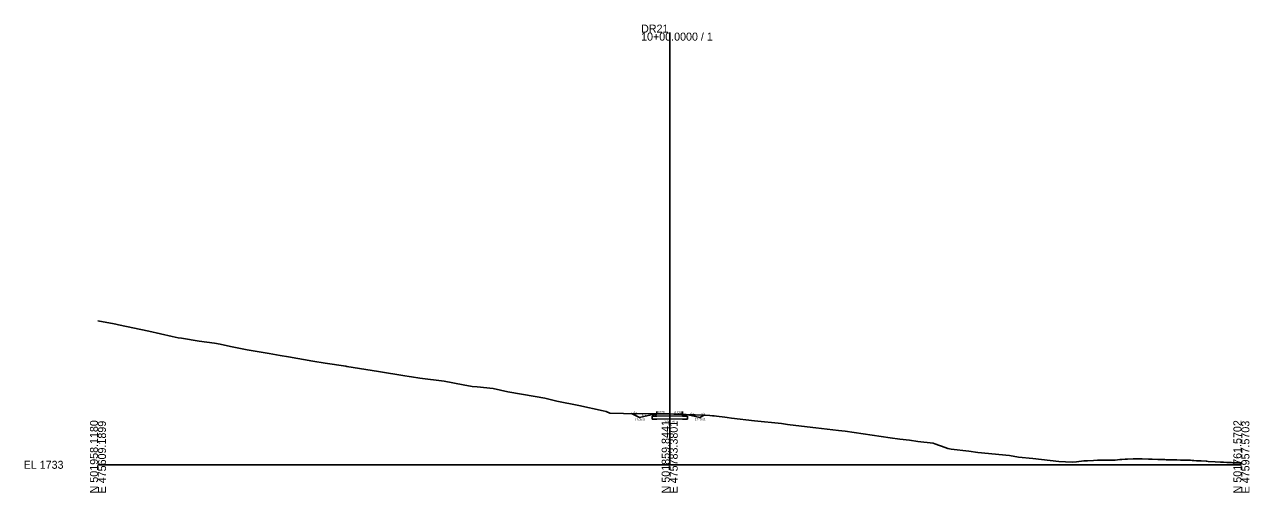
# Model space of a CAD drawing. Extents: x 78347 to 78775, y -92484 to -91314.
# Drawn here: x 78346.7 to 78775.2, y -92483.8 to -92320.1 of the extents above; entities that cross this region are included whole.
import ezdxf

# ---------------------------------------------------------------- set-up
doc = ezdxf.new("R2010")
doc.units = 0
for name, color, linetype in [('Exist Cross Section Cell', 7, 'Continuous'), ('Exist XS Center Line Elevation Label', 7, 'Continuous'), ('Exist XS Ground Line', 7, 'Continuous'), ('Prop CMT Shallow Undercut Boundary', 7, 'Continuous'), ('Prop XS Ditch Slope Text', 7, 'Continuous'), ('Prop XS Ditch Standard Text', 7, 'Continuous'), ('Prop XS Earthwork Shape', 7, 'Continuous'), ('Prop XS EOT Tick Mark', 7, 'Continuous'), ('Prop XS Finish Grade', 7, 'Continuous'), ('Prop XS Finish Grade Earthwork', 7, 'Continuous'), ('Prop XS Finish Grade Pavement', 7, 'Continuous'), ('Prop XS Pvmt Edge Slope', 7, 'Continuous'), ('Prop XS SE Text', 7, 'Continuous'), ('Prop XS Shoulder Borrow Shape', 7, 'Continuous'), ('Prop XS Side Slope Text', 7, 'Continuous'), ('Prop XS Subgrade Earthwork', 7, 'Continuous')]:
    doc.layers.add(name, color=color, linetype=linetype)

msp = doc.modelspace()

# ---------------------------------------------------------------- linework, layer by layer
at = {"layer": 'Exist Cross Section Cell'}
for p, q in [((78572.41, -92474.1), (78572.41, -92322.94)), ((78372.41, -92474.1), (78572.41, -92474.1)), ((78572.41, -92474.1), (78772.41, -92474.1))]:
    msp.add_line(p, q, dxfattribs=at)
at = {"layer": 'Exist XS Ground Line'}
for p, q in [((78372.41, -92423.71), (78378.03, -92424.8)), ((78378.03, -92424.8), (78378.7, -92424.94)), ((78378.7, -92424.94), (78379.56, -92425.12)), ((78379.56, -92425.12), (78390.18, -92427.4)), ((78390.18, -92427.4), (78398.39, -92429.19)), ((78398.39, -92429.19), (78400.48, -92429.64)), ((78400.48, -92429.64), (78401.67, -92429.86)), ((78401.67, -92429.86), (78407.83, -92430.9)), ((78407.83, -92430.9), (78413.15, -92431.57)), ((78413.15, -92431.57), (78415.17, -92431.96)), ((78415.17, -92431.96), (78418.74, -92432.72)), ((78418.74, -92432.72), (78424.64, -92433.87)), ((78424.64, -92433.87), (78432.26, -92435.18)), ((78432.26, -92435.18), (78436.12, -92435.82)), ((78436.12, -92435.82), (78439.1, -92436.34)), ((78439.1, -92436.34), (78447.6, -92437.81)), ((78447.6, -92437.81), (78451.88, -92438.57)), ((78451.88, -92438.57), (78459.09, -92439.66)), ((78459.09, -92439.66), (78459.45, -92439.73)), ((78459.45, -92439.73), (78470.57, -92441.52)), ((78470.57, -92441.52), (78479.81, -92443.02)), ((78479.81, -92443.02), (78481.24, -92443.27)), ((78481.24, -92443.27), (78482.05, -92443.38)), ((78482.05, -92443.38), (78484.96, -92443.81)), ((78484.96, -92443.81), (78493.54, -92444.9)), ((78493.54, -92444.9), (78500.16, -92446.13)), ((78500.16, -92446.13), (78503.27, -92446.66)), ((78503.27, -92446.66), (78505.02, -92446.89)), ((78505.02, -92446.89), (78510.61, -92447.45)), ((78510.61, -92447.45), (78515.82, -92448.56)), ((78515.82, -92448.56), (78525.35, -92450.21)), ((78525.35, -92450.21), (78528.68, -92450.85)), ((78528.68, -92450.85), (78532.92, -92451.9)), ((78532.92, -92451.9), (78540.6, -92453.31)), ((78540.6, -92453.31), (78549.2, -92455.23)), ((78549.2, -92455.23), (78550.15, -92455.49)), ((78550.15, -92455.49), (78551.49, -92456.07)), ((78551.49, -92456.07), (78556.26, -92456.15)), ((78556.26, -92456.15), (78568.78, -92456.27)), ((78568.78, -92456.27), (78572.41, -92456.33)), ((78572.41, -92456.33), (78573.92, -92456.36)), ((78573.92, -92456.36), (78576.67, -92456.46)), ((78576.67, -92456.46), (78577.52, -92456.47)), ((78577.52, -92456.47), (78578.21, -92456.5)), ((78578.21, -92456.5), (78586.45, -92456.89)), ((78586.45, -92456.89), (78587.35, -92456.92)), ((78587.35, -92456.92), (78587.96, -92456.98)), ((78587.96, -92456.98), (78588.78, -92457.09)), ((78588.78, -92457.09), (78591.73, -92457.41)), ((78591.73, -92457.41), (78592.56, -92457.54)), ((78592.56, -92457.54), (78593.98, -92457.83)), ((78593.98, -92457.83), (78602.04, -92458.67)), ((78602.04, -92458.67), (78611.55, -92459.66)), ((78611.55, -92459.66), (78613.64, -92459.96)), ((78613.64, -92459.96), (78614.6, -92460.07)), ((78614.6, -92460.07), (78623.5, -92461.14)), ((78623.5, -92461.14), (78631.48, -92462.07)), ((78631.48, -92462.07), (78633.82, -92462.33)), ((78633.82, -92462.33), (78649.56, -92464.7)), ((78649.56, -92464.7), (78652.98, -92465.18)), ((78652.98, -92465.18), (78656.34, -92465.54)), ((78656.34, -92465.54), (78659.17, -92466.01)), ((78659.17, -92466.01), (78664.61, -92466.59)), ((78664.61, -92466.59), (78665.22, -92466.76)), ((78665.22, -92466.76), (78668.8, -92468)), ((78668.8, -92468), (78669.66, -92468.36)), ((78669.66, -92468.36), (78670.86, -92468.58)), ((78670.86, -92468.58), (78677.08, -92469.39)), ((78677.08, -92469.39), (78680.26, -92469.79)), ((78680.26, -92469.79), (78691.31, -92470.88)), ((78691.31, -92470.88), (78694.42, -92471.38)), ((78694.42, -92471.38), (78699.45, -92471.91)), ((78699.45, -92471.91), (78708.49, -92472.9)), ((78708.49, -92472.9), (78710.84, -92473.12)), ((78714.72, -92473.1), (78717.26, -92472.73)), ((78717.26, -92472.73), (78718.11, -92472.68)), ((78718.11, -92472.68), (78718.61, -92472.67)), ((78718.61, -92472.67), (78720.71, -92472.58)), ((78720.71, -92472.58), (78722.08, -92472.49)), ((78722.08, -92472.49), (78722.86, -92472.5)), ((78722.86, -92472.5), (78728.06, -92472.5)), ((78728.06, -92472.5), (78728.21, -92472.49)), ((78728.21, -92472.49), (78729.85, -92472.27)), ((78729.85, -92472.27), (78729.95, -92472.27)), ((78729.95, -92472.27), (78730.56, -92472.22)), ((78730.56, -92472.22), (78731.71, -92472.12)), ((78731.71, -92472.12), (78732.62, -92472.08)), ((78732.62, -92472.08), (78734.59, -92472)), ((78734.59, -92472), (78734.62, -92472)), ((78734.62, -92472), (78734.78, -92472)), ((78734.78, -92472), (78734.91, -92472.01)), ((78734.91, -92472.01), (78735.63, -92472.02)), ((78735.63, -92472.02), (78737.05, -92472.05)), ((78737.05, -92472.05), (78737.36, -92472.06)), ((78737.36, -92472.06), (78737.65, -92472.07)), ((78737.65, -92472.07), (78739.94, -92472.14)), ((78739.94, -92472.14), (78740.31, -92472.16)), ((78740.31, -92472.16), (78741.15, -92472.18)), ((78741.15, -92472.18), (78743.17, -92472.23)), ((78743.17, -92472.23), (78744.72, -92472.27)), ((78744.72, -92472.27), (78745.57, -92472.3)), ((78745.57, -92472.3), (78746.05, -92472.31)), ((78746.05, -92472.31), (78747.42, -92472.35)), ((78747.42, -92472.35), (78748.92, -92472.39)), ((78748.92, -92472.39), (78749.82, -92472.41)), ((78749.82, -92472.41), (78751.05, -92472.44)), ((78751.05, -92472.44), (78751.76, -92472.46)), ((78751.76, -92472.46), (78753.04, -92472.51)), ((78753.04, -92472.51), (78754.66, -92472.54)), ((78754.66, -92472.54), (78755.15, -92472.57)), ((78755.15, -92472.57), (78755.82, -92472.6)), ((78755.82, -92472.6), (78756.68, -92472.66)), ((78756.68, -92472.66), (78757.5, -92472.71)), ((78757.5, -92472.71), (78758.38, -92472.76)), ((78758.38, -92472.76), (78760.03, -92472.85)), ((78760.03, -92472.85), (78760.17, -92472.86)), ((78760.17, -92472.86), (78760.36, -92472.87)), ((78760.36, -92472.87), (78760.79, -92472.9)), ((78760.79, -92472.9), (78763.23, -92473.03)), ((78763.23, -92473.03), (78765.1, -92473.13)), ((78710.84, -92473.12), (78713.21, -92473.14)), ((78713.21, -92473.14), (78714.72, -92473.1)), ((78765.1, -92473.13), (78765.74, -92473.17)), ((78765.74, -92473.17), (78766.1, -92473.19)), ((78766.1, -92473.19), (78767.35, -92473.26)), ((78767.35, -92473.26), (78768.96, -92473.35)), ((78768.96, -92473.35), (78769.4, -92473.37)), ((78769.4, -92473.37), (78770.19, -92473.42)), ((78770.19, -92473.42), (78771.24, -92473.47)), ((78771.24, -92473.47), (78771.84, -92473.5)), ((78771.84, -92473.5), (78772.41, -92473.54))]:
    msp.add_line(p, q, dxfattribs=at)
at = {"layer": 'Prop CMT Shallow Undercut Boundary'}
for p, q in [((78566.23, -92457.12), (78567.91, -92457.09)), ((78567.23, -92457.1), (78566.23, -92457.12)), ((78566.23, -92458.12), (78566.23, -92457.12)), ((78566.23, -92457.12), (78566.23, -92458.12)), ((78567.91, -92458.09), (78566.23, -92458.12)), ((78566.23, -92458.12), (78567.91, -92458.09)), ((78567.91, -92457.09), (78567.23, -92457.1)), ((78567.91, -92457.09), (78572.41, -92457)), ((78572.41, -92457), (78567.91, -92457.09)), ((78572.41, -92458), (78567.91, -92458.09)), ((78567.91, -92458.09), (78572.41, -92458)), ((78572.41, -92457), (78576.91, -92457.09)), ((78576.91, -92458.09), (78572.41, -92458)), ((78572.41, -92458), (78576.91, -92458.09)), ((78576.91, -92457.09), (78578.59, -92457.12)), ((78578.59, -92458.12), (78576.91, -92458.09)), ((78576.91, -92458.09), (78578.59, -92458.12)), ((78578.59, -92457.12), (78577.59, -92457.1)), ((78578.59, -92457.12), (78578.59, -92458.12)), ((78578.59, -92458.12), (78578.59, -92457.12))]:
    msp.add_line(p, q, dxfattribs=at)
msp.add_lwpolyline([(78577.59, -92457.1), (78576.91, -92457.09), (78572.41, -92457)], dxfattribs=at)
at = {"layer": 'Prop XS Earthwork Shape'}
msp.add_lwpolyline([(78559.09, -92456.18), (78568.78, -92456.27), (78572.41, -92456.33), (78573.92, -92456.36), (78576.67, -92456.46), (78577.52, -92456.47), (78578.21, -92456.5), (78584.48, -92456.8), (78582.91, -92457.58), (78578.91, -92456.58), (78578.17, -92456.53), (78577.59, -92457.1), (78576.91, -92457.09), (78572.41, -92457), (78567.91, -92457.09), (78567.23, -92457.1), (78566.65, -92456.53), (78565.91, -92456.58), (78561.91, -92457.58)], close=True, dxfattribs=at)
at = {"layer": 'Prop XS EOT Tick Mark'}
for p, q in [((78567.91, -92456.42), (78567.91, -92455.42)), ((78576.91, -92456.42), (78576.91, -92455.42))]:
    msp.add_line(p, q, dxfattribs=at)
at = {"layer": 'Prop XS Finish Grade'}
for p, q in [((78567.91, -92456.42), (78566.65, -92456.53)), ((78576.91, -92456.42), (78578.17, -92456.53))]:
    msp.add_line(p, q, dxfattribs=at)
at = {"layer": 'Prop XS Finish Grade Earthwork'}
for p, q in [((78561.91, -92457.58), (78559.09, -92456.18)), ((78565.91, -92456.58), (78561.91, -92457.58)), ((78566.65, -92456.53), (78565.91, -92456.58)), ((78578.17, -92456.53), (78578.91, -92456.58)), ((78578.91, -92456.58), (78582.91, -92457.58)), ((78582.91, -92457.58), (78584.48, -92456.8))]:
    msp.add_line(p, q, dxfattribs=at)
at = {"layer": 'Prop XS Finish Grade Pavement'}
for p, q in [((78567.91, -92456.42), (78572.41, -92456.33)), ((78572.41, -92456.33), (78576.91, -92456.42))]:
    msp.add_line(p, q, dxfattribs=at)
at = {"layer": 'Prop XS Pvmt Edge Slope'}
for p, q in [((78567.91, -92456.42), (78567.23, -92457.1)), ((78576.91, -92456.42), (78577.59, -92457.1))]:
    msp.add_line(p, q, dxfattribs=at)
at = {"layer": 'Prop XS Shoulder Borrow Shape'}
for points in [[(78567.91, -92456.42), (78567.23, -92457.1), (78566.65, -92456.53)], [(78577.59, -92457.1), (78578.17, -92456.53), (78576.91, -92456.42)]]:
    msp.add_lwpolyline(points, close=True, dxfattribs=at)
at = {"layer": 'Prop XS Subgrade Earthwork'}
for p, q in [((78567.23, -92457.1), (78566.65, -92456.53)), ((78567.91, -92457.09), (78567.23, -92457.1)), ((78572.41, -92457), (78567.91, -92457.09)), ((78576.91, -92457.09), (78572.41, -92457)), ((78576.91, -92457.09), (78577.59, -92457.1)), ((78577.59, -92457.1), (78578.17, -92456.53))]:
    msp.add_line(p, q, dxfattribs=at)

# ---------------------------------------------------------------- texts
at = {"layer": 'Exist Cross Section Cell'}
for s, p in [('10+00.0000 / 1', (78562.41, -92325.74)), ('DR21', (78562.41, -92322.94)), ('EL 1733', (78346.41, -92475.5))]:
    msp.add_text(s, height=2.8, dxfattribs=at).set_placement(p)
for s, p in [('N 501958.1180', (78372.41, -92484.1)), ('E 475609.1899', (78375.21, -92484.1)), ('N 501859.8441', (78572.41, -92484.1)), ('E 475783.3801', (78575.21, -92484.1)), ('N 501761.5702', (78772.41, -92484.1)), ('E 475957.5703', (78775.21, -92484.1))]:
    msp.add_text(s, height=2.8, rotation=90, dxfattribs=at).set_placement(p)
at = {"layer": 'Exist XS Center Line Elevation Label'}
msp.add_text('1750.76', height=0.75, dxfattribs=at).set_placement((78570.51, -92459.37))
at = {"layer": 'Prop XS Ditch Slope Text'}
for rotation, p in [(345.9638, (78579.48, -92456.5)), (14.0362, (78562.73, -92457.1))]:
    msp.add_text('4:1', height=0.75, rotation=rotation, dxfattribs=at).set_placement(p)
at = {"layer": 'Prop XS Ditch Standard Text'}
for p in [(78560.24, -92458.72), (78581.24, -92458.53)]:
    msp.add_text('1749.51', height=0.75, dxfattribs=at).set_placement(p)
at = {"layer": 'Prop XS SE Text'}
for rotation, p in [(1.1458, (78568.04, -92456.07)), (358.8542, (78574.08, -92456.15))]:
    msp.add_text('0.020', height=0.75, rotation=rotation, dxfattribs=at).set_placement(p)
at = {"layer": 'Prop XS Side Slope Text'}
for rotation, p in [(333.4349, (78559.56, -92456.02)), (26.5651, (78583.64, -92457.06))]:
    msp.add_text('2:1', height=0.75, rotation=rotation, dxfattribs=at).set_placement(p)

doc.saveas('drawing.dxf')
